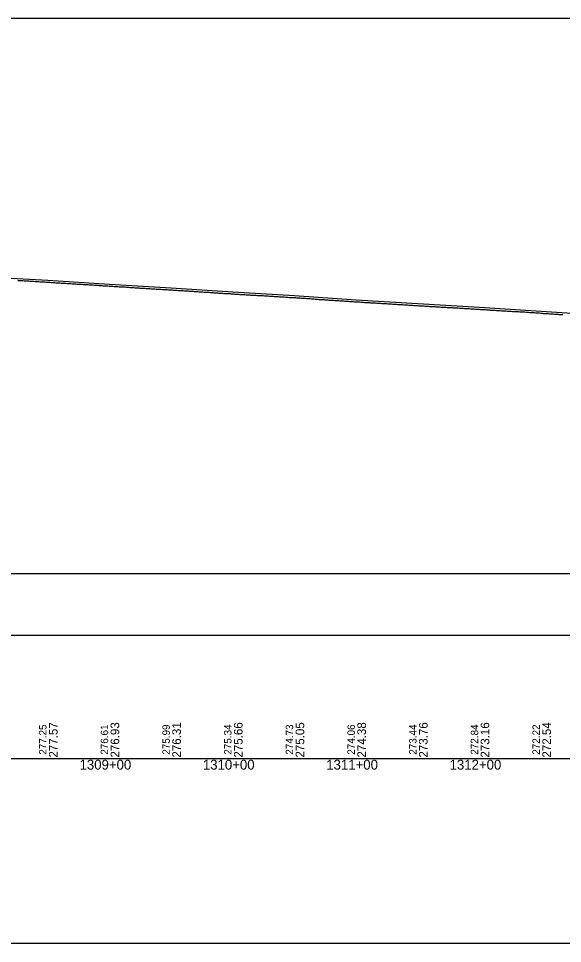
# Model space of a CAD drawing. Extents: x -3627 to 47473, y 2850 to 4350.
# Drawn here: x 18204 to 18645, y 2850 to 3600 of the extents above; entities that cross this region are included whole.
import ezdxf

# ---------------------------------------------------------------- set-up
doc = ezdxf.new("R2010")
doc.units = 0
for name, color, linetype in [('RD_DDB_Profile_EX', 7, 'Continuous'), ('RD_DDB_Profile_PR', 7, 'Continuous'), ('RD_DDB_StaTX', 7, 'Continuous'), ('RD_DDB_StripGrade', 7, 'Continuous'), ('RD_GPK_Profile_Cell', 7, 'Continuous'), ('RD_SHT_ShtClip', 7, 'Continuous')]:
    doc.layers.add(name, color=color, linetype=linetype)

msp = doc.modelspace()

# ---------------------------------------------------------------- linework, layer by layer
at = {"layer": 'RD_DDB_Profile_EX'}
for points in [[(18203.109658, 3387.62957), (18204.1116, 3387.601755), (18205.105749, 3387.563035), (18206.107696, 3387.52382), (18207.109642, 3387.47014), (18208.110305, 3387.407365), (18209.107784, 3387.3952), (18210.109744, 3387.306385), (18211.110409, 3387.217455), (18212.112363, 3387.16679), (18213.106545, 3387.142235), (18214.112576, 3387.08019), (18215.114527, 3386.99153), (18216.115156, 3386.90273), (18217.112768, 3386.877865), (18218.114733, 3386.814655), (18219.115363, 3386.738285), (18220.117322, 3386.72499), (18221.111531, 3386.599665), (18222.113494, 3386.53634), (18223.115456, 3386.51024), (18224.118229, 3386.4342), (18225.132242, 3386.359405), (18226.160731, 3386.297975), (18227.162698, 3386.234505), (18228.161478, 3386.18585), (18229.157052, 3386.148415), (18230.163029, 3386.060605), (18231.157792, 3385.99892), (18232.157359, 3385.912195), (18233.157186, 3385.836585), (18234.156759, 3385.77489), (18235.161954, 3385.725555), (18236.1575, 3385.66302), (18237.157062, 3385.576365), (18238.158241, 3385.4885), (18239.157801, 3385.43932), (18240.157654, 3385.41395), (18241.158539, 3385.339875), (18242.154062, 3385.32749), (18243.157962, 3385.240135), (18244.15348, 3385.152375), (18245.152234, 3385.053635), (18246.158256, 3385.015905), (18247.151668, 3384.991705), (18248.158996, 3384.942075), (18249.15449, 3384.85417), (18250.151948, 3384.76724), (18251.153928, 3384.692285), (18252.153463, 3384.617265), (18253.148943, 3384.617215), (18254.153688, 3384.567045), (18255.149171, 3384.466995), (18256.155204, 3384.36707), (18257.150687, 3384.31702), (18258.150203, 3384.317745)], [(18258.150203, 3384.317745), (18259.156242, 3384.26782), (18260.150435, 3384.217525), (18261.156472, 3384.1676), (18262.151948, 3384.003675), (18263.151454, 3383.992235), (18264.15346, 3383.941655), (18265.15169, 3383.892055), (18266.147159, 3383.81802), (18267.153199, 3383.730085), (18268.148668, 3383.68004), (18269.154708, 3383.606135), (18270.150177, 3383.50608), (18271.148396, 3383.418575), (18272.154441, 3383.368655), (18273.149902, 3383.368605), (18274.149377, 3383.243115), (18275.151407, 3383.18058), (18276.149624, 3383.119145), (18277.151651, 3383.080375), (18278.153678, 3382.97971), (18279.149155, 3382.91763), (18280.151194, 3382.878995), (18281.157221, 3382.803255), (18282.149344, 3382.71688), (18283.151369, 3382.653975), (18284.153393, 3382.60317), (18285.148905, 3382.52759), (18286.150942, 3382.502305), (18287.156947, 3382.426985), (18288.157669, 3382.338465), (18289.153208, 3382.32602), (18290.155241, 3382.325345), (18291.157275, 3382.199605), (18292.152839, 3382.112075), (18293.157498, 3382.06187), (18294.158684, 3381.99905), (18295.154727, 3381.974855), (18296.153756, 3381.87484), (18297.156266, 3381.81235), (18298.148832, 3381.713005), (18299.15134, 3381.650575), (18300.155687, 3381.601705), (18301.156879, 3381.50144), (18302.150781, 3381.465525), (18303.151976, 3381.389835), (18304.152363, 3381.315505), (18305.148377, 3381.26641), (18306.151501, 3381.217425), (18307.153998, 3381.205265), (18308.14662, 3381.11827), (18309.149115, 3381.068275), (18310.149533, 3380.98065), (18311.150732, 3380.89399), (18312.148727, 3380.858435), (18313.149931, 3380.796085), (18314.150371, 3380.708365), (18315.14507, 3380.65893), (18316.145517, 3380.559205), (18317.143563, 3380.56147), (18318.144773, 3380.499305), (18319.145241, 3380.43779), (18320.13993, 3380.38543), (18321.144545, 3380.31324), (18322.14048, 3380.252485), (18323.139716, 3380.214015), (18324.142188, 3380.16398), (18325.139055, 3380.10433), (18326.141522, 3380.0158), (18327.134236, 3379.97805), (18328.1367, 3379.889475), (18329.141409, 3379.790575), (18330.136069, 3379.741025), (18331.1366, 3379.691205), (18332.137822, 3379.629525), (18333.136011, 3379.57026), (18334.138463, 3379.481435), (18335.13189, 3379.431625), (18336.133801, 3379.353335), (18337.139931, 3379.34216), (18338.135271, 3379.26467), (18339.135264, 3379.225495), (18340.130611, 3379.191495), (18341.136736, 3379.102915), (18342.137403, 3379.013315), (18343.132762, 3378.951885), (18344.134674, 3378.91259), (18345.134238, 3378.863325), (18346.136154, 3378.762635), (18347.138069, 3378.70044), (18348.137633, 3378.628355), (18349.139552, 3378.53899), (18350.137867, 3378.50104), (18351.133239, 3378.478075), (18352.139347, 3378.378185), (18353.134719, 3378.25105), (18354.140827, 3378.239695), (18355.134251, 3378.162755), (18356.133802, 3378.113505), (18357.135729, 3378.012805), (18358.134042, 3377.974715)], [(18358.134042, 3377.974715), (18359.135966, 3377.912615), (18360.135517, 3377.85199), (18361.130877, 3377.75195), (18362.136992, 3377.702045), (18363.132351, 3377.652005), (18364.138466, 3377.540725), (18365.133825, 3377.44068), (18366.132126, 3377.402635), (18367.134069, 3377.363255), (18368.133597, 3377.291365), (18369.135543, 3377.240525), (18370.133137, 3377.15297), (18371.128484, 3377.10293), (18372.134606, 3377.05303), (18373.128733, 3376.95273), (18374.136074, 3376.90309), (18375.130708, 3376.89226), (18376.128305, 3376.782225), (18377.129549, 3376.72065), (18378.130265, 3376.64426), (18379.131515, 3376.56622), (18380.12913, 3376.556135), (18381.123741, 3376.5176), (18382.129206, 3376.407135), (18383.12381, 3376.296605), (18384.126943, 3376.235035), (18385.131227, 3376.1854), (18386.125831, 3376.13589), (18387.127089, 3376.096485), (18388.125916, 3376.058755), (18389.125996, 3375.98637), (18390.122453, 3375.93662), (18391.127945, 3375.858965), (18392.122537, 3375.80938), (18393.123802, 3375.75906), (18394.121466, 3375.69935), (18395.122731, 3375.65979), (18396.125833, 3375.580915), (18397.124667, 3375.532005), (18398.125935, 3375.43173), (18399.119357, 3375.43188), (18400.124886, 3375.432345), (18401.119469, 3375.33269), (18402.122557, 3375.282245), (18403.120242, 3375.23313), (18404.121513, 3375.122205), (18405.122781, 3375.071905), (18406.12164, 3375.07308), (18407.122911, 3374.95158), (18408.118137, 3374.912155), (18409.123692, 3374.823255), (18410.118263, 3374.763095), (18411.119537, 3374.6811), (18412.117258, 3374.682375), (18413.120316, 3374.602765), (18414.12159, 3374.481335), (18415.120456, 3374.432885), (18416.121733, 3374.39295), (18417.11516, 3374.311775), (18418.120749, 3374.26251), (18419.117076, 3374.223195), (18420.118994, 3374.12222), (18421.116727, 3374.073565), (18422.118639, 3373.983025), (18423.118142, 3373.89443), (18424.118289, 3373.87296), (18425.117797, 3373.824065), (18426.114103, 3373.745), (18427.118583, 3373.674735), (18428.113759, 3373.654085), (18429.119993, 3373.52486), (18430.115168, 3373.48514), (18431.112912, 3373.4762), (18432.114828, 3373.435495), (18433.115425, 3373.297025), (18434.115609, 3373.256615), (18435.115095, 3373.19736), (18436.110249, 3373.14734), (18437.116496, 3373.06782), (18438.10992, 3372.99768), (18439.109392, 3372.88859), (18440.112418, 3372.84806), (18441.110166, 3372.739235), (18442.112093, 3372.688295), (18443.111558, 3372.62933), (18444.109319, 3372.53072), (18445.111243, 3372.42972), (18446.110706, 3372.370925), (18447.113717, 3372.28016), (18448.111479, 3372.18156), (18449.106588, 3372.14145), (18450.112862, 3372.08171), (18451.106284, 3372.03194), (18452.105731, 3371.99292), (18453.107666, 3371.94197), (18454.106499, 3371.813125), (18455.108434, 3371.731965), (18456.107873, 3371.68279), (18457.102957, 3371.623015), (18458.107585, 3371.56359)], [(18458.107585, 3371.56359), (18459.102665, 3371.51358), (18460.110008, 3371.39453), (18461.103428, 3371.38504), (18462.109724, 3371.33522), (18463.104796, 3371.254595), (18464.106133, 3371.18333), (18465.10121, 3371.133325), (18466.105849, 3371.003015), (18467.101966, 3370.993495), (18468.102258, 3370.883265), (18469.109602, 3370.843295), (18470.103021, 3370.743445), (18471.103305, 3370.68321), (18472.103784, 3370.593895), (18473.104074, 3370.593395), (18474.100191, 3370.533895), (18475.100481, 3370.44307), (18476.106777, 3370.393185), (18477.101247, 3370.32416), (18478.103186, 3370.263645), (18479.102012, 3370.20541), (18480.103951, 3370.164215), (18481.10423, 3370.123325), (18482.104717, 3370.0341), (18483.105002, 3369.933555), (18484.101123, 3369.86281), (18485.105775, 3369.80337), (18486.100841, 3369.753365), (18487.102177, 3369.71277), (18488.104112, 3369.64273), (18489.102945, 3369.564875), (18490.10488, 3369.483465), (18491.098301, 3369.47393), (18492.105648, 3369.393625), (18493.099069, 3369.343775), (18494.102054, 3369.293305), (18495.106703, 3369.243575), (18496.101772, 3369.18389), (18497.103105, 3369.08355), (18498.098179, 3369.043245), (18499.103875, 3369.034035), (18500.105807, 3368.933325), (18501.099229, 3368.873775), (18502.104932, 3368.78398), (18503.099999, 3368.7243), (18504.101331, 3368.68363), (18505.10077, 3368.594085), (18506.101055, 3368.533915), (18507.097169, 3368.484105), (18508.101832, 3368.3844), (18509.097936, 3368.374975), (18510.099873, 3368.28388), (18511.104531, 3368.184175), (18512.10064, 3368.134365), (18513.100928, 3368.074145), (18514.100366, 3368.034655), (18515.101701, 3367.98431), (18516.096764, 3367.92466), (18517.102474, 3367.825195), (18518.09753, 3367.70399), (18519.097825, 3367.714955), (18520.105175, 3367.655715), (18521.098598, 3367.56552), (18522.100526, 3367.524355), (18523.099371, 3367.47565), (18524.101299, 3367.415255), (18525.095762, 3367.315675), (18526.102072, 3367.23499), (18527.095494, 3367.22558), (18528.098465, 3367.13464), (18529.103141, 3367.115755), (18530.098195, 3367.075335), (18531.09953, 3366.965345), (18532.098968, 3366.906765), (18533.100305, 3366.81591), (18534.095357, 3366.765905), (18535.100044, 3366.7258), (18536.096126, 3366.626005), (18537.096429, 3366.60625), (18538.10378, 3366.606655), (18539.097204, 3366.48777), (18540.099128, 3366.427165), (18541.10046, 3366.376655), (18542.102381, 3366.28529), (18543.095805, 3366.235515), (18544.098782, 3366.204235), (18545.099048, 3366.12309), (18546.094132, 3366.07308), (18547.101482, 3365.983165), (18548.103409, 3365.972665), (18549.103663, 3365.92209), (18550.098759, 3365.872075), (18551.100686, 3365.781215), (18552.102613, 3365.73051), (18553.102839, 3365.67998), (18554.097963, 3365.58997), (18555.104229, 3365.55007), (18556.105536, 3365.4998), (18557.100663, 3365.499785), (18558.10259, 3365.3992)], [(18558.10259, 3365.3992), (18559.104517, 3365.288475), (18560.104712, 3365.27781), (18561.099867, 3365.237975), (18562.101794, 3365.17709), (18563.108034, 3365.1272), (18564.108208, 3365.076675), (18565.103379, 3364.986935), (18566.106421, 3364.936485), (18567.108348, 3364.89622), (18568.101771, 3364.806715), (18569.103698, 3364.75619), (18570.105625, 3364.716145), (18571.111839, 3364.60574), (18572.105264, 3364.55586), (18573.107184, 3364.494815), (18574.109105, 3364.454805), (18575.112179, 3364.35444), (18576.105602, 3364.25456), (18577.111803, 3364.233445), (18578.107028, 3364.18342), (18579.11323, 3364.1047), (18580.106653, 3363.99424), (18581.106151, 3364.02388), (18582.108078, 3363.98374), (18583.107571, 3363.84497), (18584.108851, 3363.794715), (18585.108342, 3363.734915), (18586.101763, 3363.63506), (18587.109112, 3363.62494), (18588.102534, 3363.5751), (18589.109883, 3363.485805), (18590.103305, 3363.38595), (18591.102144, 3363.307585), (18592.104075, 3363.296725), (18593.102914, 3363.247725), (18594.104846, 3363.157415), (18595.103685, 3363.058315), (18596.098841, 3362.998115), (18597.103354, 3362.988195), (18598.099604, 3362.88837), (18599.104129, 3362.83864), (18600.098648, 3362.818795), (18601.098107, 3362.7297), (18602.099418, 3362.67937), (18603.098875, 3362.63019), (18604.100189, 3362.54988), (18605.099643, 3362.54062), (18606.100959, 3362.440315), (18607.100411, 3362.351455), (18608.0949, 3362.35191), (18609.101179, 3362.32179), (18610.0946, 3362.24166), (18611.100277, 3362.151925), (18612.095368, 3362.101915), (18613.094201, 3362.04321), (18614.096136, 3362.032785), (18615.094969, 3361.97432), (18616.096904, 3361.91382), (18617.095737, 3361.81522), (18618.090797, 3361.72484), (18619.096505, 3361.684965), (18620.089926, 3361.644695), (18621.097273, 3361.53545), (18622.090694, 3361.495145), (18623.092629, 3361.4349), (18624.091462, 3361.34559), (18625.086499, 3361.245585), (18626.09223, 3361.227135), (18627.08726, 3361.13658), (18628.091977, 3361.02745), (18629.088021, 3360.93707), (18630.09275, 3360.87798), (18631.087769, 3360.759205), (18632.093522, 3360.687855), (18633.088535, 3360.706545), (18634.083547, 3360.647195), (18635.0893, 3360.619735), (18636.084306, 3360.53834), (18637.090066, 3360.43883), (18638.085064, 3360.348095), (18639.089832, 3360.32989), (18640.085823, 3360.280095), (18641.090602, 3360.18962), (18642.085589, 3360.13042), (18643.079999, 3360.08997), (18644.086352, 3359.999265), (18645.079772, 3359.917705)]]:
    msp.add_lwpolyline(points, dxfattribs=at)
at = {"layer": 'RD_DDB_Profile_PR'}
msp.add_lwpolyline([(17727.33, 3396.808), (17777.33, 3397.9145), (17827.33, 3398.0085), (17877.33, 3398.4425), (17927.33, 3398.187), (17977.33, 3397.6525), (18027.33, 3396.189), (18077.33, 3394.499), (18127.33, 3392.3215), (18177.33, 3390.4535), (18227.33, 3387.8265), (18277.33, 3384.6625), (18327.33, 3381.561), (18377.33, 3378.3055), (18427.33, 3375.2705), (18477.33, 3371.9105), (18527.33, 3368.8045), (18577.33, 3365.8225), (18627.33, 3362.71), (18677.33, 3359.498)], dxfattribs=at)
at = {"layer": 'RD_GPK_Profile_Cell'}
msp.add_line((1000, 3000), (46705.077602, 3000), dxfattribs=at)
at = {"layer": 'RD_SHT_ShtClip'}
for points in [[(17453.33, 3600), (17453.33, 3100), (18953.33, 3100), (18953.33, 3100), (18953.33, 3600), (18953.33, 3600)], [(17433.33, 3150), (18973.33, 3150), (18973.33, 2850), (17433.33, 2850)]]:
    msp.add_lwpolyline(points, close=True, dxfattribs=at)

# ---------------------------------------------------------------- texts
at = {"layer": 'RD_DDB_StaTX'}
for s, p in [('1309+00', (18253.125471, 2991)), ('1310+00', (18353.125471, 2991)), ('1311+00', (18453.125471, 2991)), ('1312+00', (18553.125471, 2991))]:
    msp.add_text(s, height=8, dxfattribs=at).set_placement(p)
at = {"layer": 'RD_DDB_StripGrade'}
for s, height, p in [('277.25', 6, (18226.33, 3003.073688)), ('277.57', 7, (18235.33, 3000.75)), ('276.61', 6, (18276.33, 3003.073688)), ('276.93', 7, (18285.33, 3000.75)), ('275.99', 6, (18326.33, 3003.073688)), ('276.31', 7, (18335.33, 3000.75)), ('275.34', 6, (18376.33, 3003.073688)), ('275.66', 7, (18385.33, 3000.75)), ('274.73', 6, (18426.33, 3003.073688)), ('275.05', 7, (18435.33, 3000.75)), ('274.06', 6, (18476.33, 3003.073688)), ('274.38', 7, (18485.33, 3000.75)), ('273.44', 6, (18526.33, 3003.073688)), ('273.76', 7, (18535.33, 3000.75)), ('272.84', 6, (18576.33, 3003.073688)), ('273.16', 7, (18585.33, 3000.75)), ('272.22', 6, (18626.33, 3003.073688)), ('272.54', 7, (18635.33, 3000.75))]:
    msp.add_text(s, height=height, rotation=90, dxfattribs=at).set_placement(p)

doc.saveas('drawing.dxf')
